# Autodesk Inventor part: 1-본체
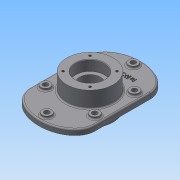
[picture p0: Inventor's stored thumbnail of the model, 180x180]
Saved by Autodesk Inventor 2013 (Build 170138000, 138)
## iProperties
Created: 2015-02
Part Number: 1-본체
Material: 일반
Document SubType Name: Modeling
Designer: Administrator
Density: 1 g/cm^3
Author: Administrator
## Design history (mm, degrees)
sketch "스케치1"
  geometry: L1 (70, -60)-(-70, -60); L2 (-70, -60)-(-70, 60); L3 (-70, 60)-(70, 60); L4 (70, 60)-(70, -60); L5 (70, -60)-(-70, 60); L6 (-70, -60)-(70, 60); 7 further points; 2 other entities
  constraints: 12 end point, 4 midpoint, 3 horizontal, 2 coincident, 2 parallel, 2 vertical alignment, 1 perpendicular, 8 other
  dimensions: "d0" = 140 distance of L1.start L1.end; "d2" = 120 distance of L3.end L1.start; "d3" = 50 distance from line of point (0, 110) L3; "d4" = 50 distance from line of point (0, -110) L1
extrude "돌출1" new body sketch "스케치1" distance "d5" = 12; taper "d6" = 0 deg
sketch "스케치2"
  geometry: L1 (-70, 60)-(-70, -60) reference; L2 (70, -60)-(70, 60) reference; L3 (-53, 60)-(-53, -60); L4 (53, -60)-(53, 60); C1 r 10 at (53, 42.733); C2 r 10 at (53, -42.733); C3 r 10 at (0, 93); C4 r 10 at (0, -93); 3 further points; 2 other entities
  constraints: 4 centre point, 4 end point, 3 parallel, 2 equal radius, 2 point on line, 2 vertical alignment, 10 other
  dimensions: "d7" = 17 distance between parallel lines of L2 L4; "d8" = 85.46667 distance of C2.centre C1.centre; "d9" = 42.73333 vertical distance of C2.centre point (0, 0); "d10" = 20 diameter of C1; "d13" = 20 diameter of C3
extrude "돌출2" join sketch "스케치2" distance "d11" = 5; taper "d12" = 0 deg
extrude "돌출3" join sketch "스케치2" distance "d14" = 5; taper "d15" = 0 deg
node "작업 평면1"
sketch "스케치4"
  geometry: C1 r 50 at (0, 0); 1 further point
  constraints: 1 centre point, 1 coincident
  dimensions: "d17" = 100 diameter of C1
extrude "돌출4" join sketch "스케치4" distance "d19" = 70; taper "d20" = 0 deg
sketch "스케치5"
  geometry: C1 r 50 at (0, 0) reference; 1 further point
  constraints: 1 coincident
hole "구멍1" sketch "스케치5" at (0, 0) diameter "d21" = 45; stored, may be unused: countersink angle "d25" = 90 deg, drill point angle "d27" = 118 deg; dims "d22" = 6, "d23" = 62, "d24" = 22, "d26" = 8
hole "구멍2" diameter "d30" = 62; stored, may be unused: countersink angle "d34" = 90 deg, drill point angle "d36" = 0 deg; dims "d28" = 10, "d29" = 10, "d31" = 6, "d32" = 62, "d33" = 22, "d35" = 22
sketch "스케치6"
  geometry: C1 r 31 at (0, 0) reference; C2 r 50 at (0, 0) reference; A1 r 41 centre (0, 0) between (-28.991, 28.991) and (0, 41)
  constraints: 2 point on circle, 1 centre point, 1 coincident, 1 vertical alignment
  dimensions: "d37" = 82 diameter of A1; "d39" = 45 deg dimension on C1.centre A1.start A1.end
hole "구멍3" sketch "스케치6" at (-28.991, 28.991) diameter "d41" = 5.134; stored, may be unused: countersink angle "d45" = 90 deg, drill point angle "d47" = 118 deg; dims "d42" = 10, "d43" = 62, "d44" = 22, "d46" = 13
node "작업 평면2"
sketch "스케치7"
  geometry: C1 r 10 at (0, 0) reference; C2 r 10 at (-53, -50.267) reference; C3 r 10 at (53, -50.267) reference; C4 r 10 at (-53, -135.733) reference; C5 r 10 at (0, -186) reference; C6 r 10 at (53, -135.733) reference; 7 further points
  constraints: 6 coincident
hole "구멍4" sketch "스케치7" at (0, 0), (-53, -50.267), (53, -50.267), (53, -135.733), (-53, -135.733), (0, -186) diameter "d51" = 11; stored, may be unused: countersink angle "d55" = 90 deg, drill point angle "d57" = 0 deg; dims "d52" = 10, "d53" = 62, "d54" = 22, "d56" = 13
sketch "스케치8"
  geometry: C1 r 50 at (0, 0) reference; 1 further point
  constraints: 1 vertical alignment, 1 other
  dimensions: "d58" = 65 distance of C1.centre point (0, 65)
feature "엠보싱1" sketch "스케치8" dims "d0" = 140, "d2" = 120, "d3" = 50, "d4" = 50, "d59" = 1, "d60" = 0
fillet "모깎기1" dims "d61" = 3
fillet "모깎기2" dims "d62" = 0.3
fillet "모깎기3" dims "d63" = 3
chamfer "모따기1" distance "d64" = 1; stored, may be unused: second distance "d65" = 2, angle "d66" = 45 deg
node "솔리드1"
mirror "대칭1"
pattern_circular "원형 패턴1" dims angle "d49" = 360 deg
mirror "대칭2"
node "투영된 루프1"
node "투영된 루프2"
node "투영된 루프3"
node "투영된 루프4"
node "투영된 루프5"
other parameters: "d16" = 23
